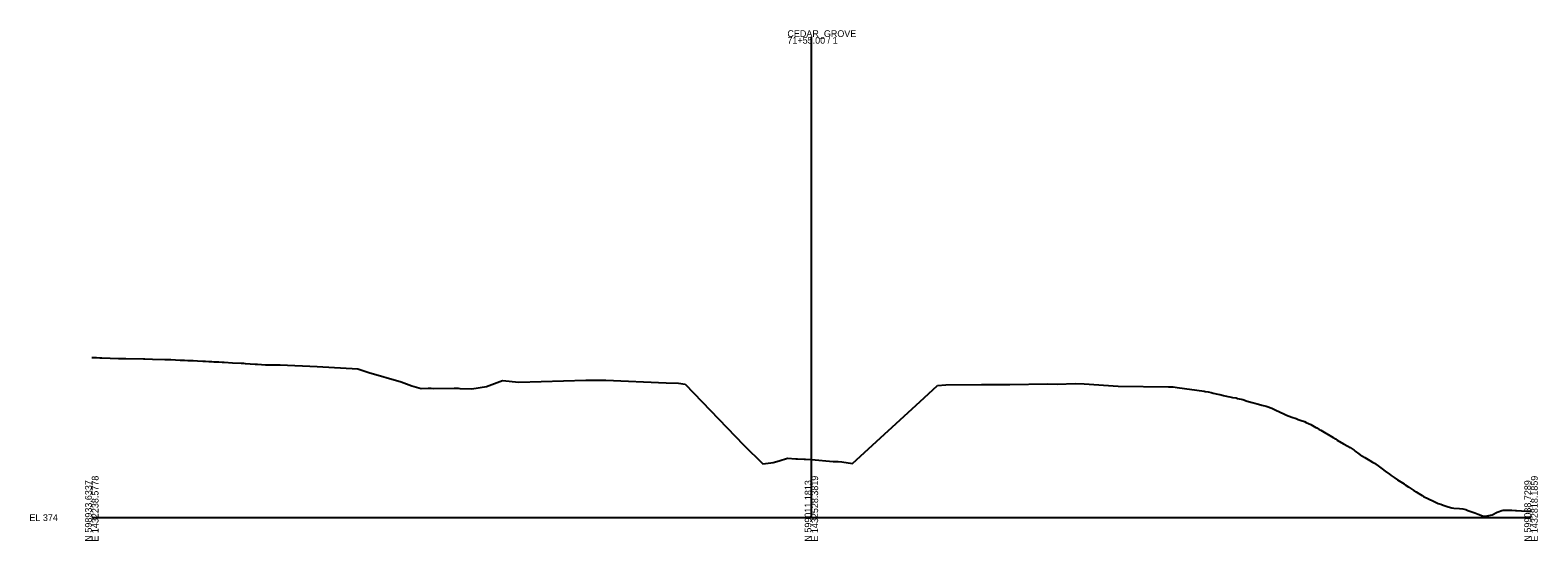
# Model space of a CAD drawing. Extents: x -26 to 2203, y -10 to 12201.
# Drawn here: x 1574 to 2203, y -10 to 203 of the extents above; entities that cross this region are included whole.
import ezdxf

# ---------------------------------------------------------------- set-up
doc = ezdxf.new("R2010")
doc.units = 0
doc.layers.add('DESIGN - SHEET - Light Grid', color=7, linetype='Continuous')
doc.layers.add('SURVEY - GROUND - Top of Ground', color=7, linetype='Continuous')

msp = doc.modelspace()

# ---------------------------------------------------------------- linework, layer by layer
at = {"layer": 'DESIGN - SHEET - Light Grid'}
for p, q in [((1900, 0), (1900, 200.49)), ((1600, 0), (1900, 0)), ((1900, 0), (2200, 0))]:
    msp.add_line(p, q, dxfattribs=at)
at = {"layer": 'SURVEY - GROUND - Top of Ground'}
for p, q in [((1600, 66.83), (1600.82, 66.79)), ((1600.82, 66.79), (1601.9, 66.75)), ((1601.9, 66.75), (1603.41, 66.69)), ((1603.41, 66.69), (1604.13, 66.66)), ((1604.13, 66.66), (1611.17, 66.43)), ((1611.17, 66.43), (1614.15, 66.32)), ((1614.15, 66.32), (1621.52, 66.27)), ((1621.52, 66.27), (1622.09, 66.24)), ((1622.09, 66.24), (1625.29, 66.14)), ((1625.29, 66.14), (1630.49, 66)), ((1630.49, 66), (1631.1, 65.96)), ((1631.1, 65.96), (1631.88, 65.93)), ((1631.88, 65.93), (1632.89, 65.89)), ((1632.89, 65.89), (1636.81, 65.71)), ((1636.81, 65.71), (1638.65, 65.66)), ((1638.65, 65.66), (1640.1, 65.58)), ((1640.1, 65.58), (1642.23, 65.5)), ((1642.23, 65.5), (1644.01, 65.37)), ((1644.01, 65.37), (1646.34, 65.24)), ((1646.34, 65.24), (1647.4, 65.21)), ((1647.4, 65.21), (1648.86, 65.16)), ((1648.86, 65.16), (1649.99, 65.1)), ((1649.99, 65.1), (1650.9, 65.05)), ((1650.9, 65.05), (1652.58, 64.96)), ((1652.58, 64.96), (1652.94, 64.94)), ((1652.94, 64.94), (1654.3, 64.86)), ((1654.3, 64.86), (1655.17, 64.82)), ((1655.17, 64.82), (1658.69, 64.63)), ((1658.69, 64.63), (1662.23, 64.44)), ((1662.23, 64.44), (1662.93, 64.4)), ((1662.93, 64.4), (1663.3, 64.38)), ((1663.3, 64.38), (1663.98, 64.32)), ((1663.98, 64.32), (1668.11, 64)), ((1668.11, 64), (1668.51, 63.98)), ((1668.51, 63.98), (1669.1, 63.96)), ((1669.1, 63.96), (1672.37, 63.75)), ((1672.37, 63.75), (1678.59, 63.7)), ((1678.59, 63.7), (1694.02, 63.02)), ((1694.02, 63.02), (1710.9, 62.12)), ((1710.9, 62.12), (1715.55, 60.53)), ((1715.55, 60.53), (1728.91, 56.58)), ((1728.91, 56.58), (1733.49, 55.01)), ((1764.59, 54.71), (1771.19, 57.16)), ((1771.19, 57.16), (1778.02, 56.5)), ((1778.02, 56.5), (1806.01, 57.38)), ((1806.01, 57.38), (1808.13, 57.34)), ((1808.13, 57.34), (1814.31, 57.27)), ((1814.31, 57.27), (1839.43, 56.26)), ((1733.49, 55.01), (1737.26, 53.86)), ((1737.26, 53.86), (1740.18, 53.97)), ((1740.18, 53.97), (1741.55, 53.93)), ((1741.55, 53.93), (1742.51, 53.92)), ((1742.51, 53.92), (1751.03, 54.01)), ((1751.03, 54.01), (1751.57, 53.98)), ((1751.57, 53.98), (1752.73, 53.98)), ((1752.73, 53.98), (1753.42, 53.87)), ((1753.42, 53.87), (1758.4, 53.76)), ((1758.4, 53.76), (1764.59, 54.71)), ((1839.43, 56.26), (1844.6, 56.05)), ((1844.6, 56.05), (1847.35, 55.63)), ((1847.35, 55.63), (1871.78, 30.29)), ((1947.01, 49.9), (1952.51, 55.14)), ((1952.51, 55.14), (1955.97, 55.42)), ((1955.97, 55.42), (1970.92, 55.59)), ((1970.92, 55.59), (1978.28, 55.47)), ((1978.28, 55.47), (1982.74, 55.48)), ((1982.74, 55.48), (1998.38, 55.76)), ((1998.38, 55.76), (2002.63, 55.73)), ((2002.63, 55.73), (2009.95, 55.93)), ((2009.95, 55.93), (2013.71, 55.76)), ((2013.71, 55.76), (2027.9, 54.84)), ((2027.9, 54.84), (2048.8, 54.51)), ((2048.8, 54.51), (2050.87, 54.5)), ((2050.87, 54.5), (2052.5, 54.32)), ((2052.5, 54.32), (2063.67, 52.72)), ((2063.67, 52.72), (2064.09, 52.65)), ((2064.09, 52.65), (2065.38, 52.42)), ((2065.38, 52.42), (2066.68, 52.17)), ((2066.68, 52.17), (2067.42, 51.95)), ((2067.42, 51.95), (2069.46, 51.47)), ((2069.46, 51.47), (2070.2, 51.3)), ((2070.2, 51.3), (2071.85, 50.92)), ((2071.85, 50.92), (2073.55, 50.56)), ((2073.55, 50.56), (2074.44, 50.38)), ((2074.44, 50.38), (2075.59, 50.15)), ((1917.13, 22.6), (1947.01, 49.9)), ((2075.59, 50.15), (2077.03, 49.9)), ((2077.03, 49.9), (2077.63, 49.75)), ((2077.63, 49.75), (2079.87, 49.24)), ((2079.87, 49.24), (2081.71, 48.61)), ((2081.71, 48.61), (2082.21, 48.46)), ((2082.21, 48.46), (2083.76, 48.02)), ((2083.76, 48.02), (2084.8, 47.73)), ((2084.8, 47.73), (2085.8, 47.5)), ((2085.8, 47.5), (2087.38, 47.08)), ((2087.38, 47.08), (2087.84, 46.97)), ((2087.84, 46.97), (2089.55, 46.54)), ((2089.55, 46.54), (2089.97, 46.42)), ((2089.97, 46.42), (2091.92, 45.67)), ((2091.92, 45.67), (2092.56, 45.37)), ((2092.56, 45.37), (2093.66, 44.83)), ((2093.66, 44.83), (2095.15, 44.1)), ((2095.15, 44.1), (2097.19, 43.17)), ((2097.19, 43.17), (2097.74, 42.91)), ((2097.74, 42.91), (2098.05, 42.78)), ((2098.05, 42.78), (2099.22, 42.34)), ((2099.22, 42.34), (2100.32, 41.92)), ((2100.32, 41.92), (2102.13, 41.29)), ((2102.13, 41.29), (2102.91, 40.99)), ((2102.91, 40.99), (2104.17, 40.54)), ((2104.17, 40.54), (2105.5, 40.03)), ((2105.5, 40.03), (2106.22, 39.71)), ((2106.22, 39.71), (2108.26, 38.79)), ((2108.26, 38.79), (2108.89, 38.44)), ((2108.89, 38.44), (2110.3, 37.64)), ((2110.3, 37.64), (2110.68, 37.42)), ((2110.68, 37.42), (2111.61, 36.81)), ((2111.61, 36.81), (2112.34, 36.41)), ((2112.34, 36.41), (2117.48, 33.41)), ((2117.48, 33.41), (2118.44, 32.85)), ((2118.44, 32.85), (2119.24, 32.37)), ((2119.24, 32.37), (2121.85, 30.78)), ((1871.78, 30.29), (1879.77, 22.48)), ((2121.85, 30.78), (2123.62, 29.75)), ((2123.62, 29.75), (2124.59, 29.18)), ((2124.59, 29.18), (2126.2, 28.07)), ((2126.2, 28.07), (2126.63, 27.78)), ((2126.63, 27.78), (2128.24, 26.64)), ((2128.24, 26.64), (2128.79, 26.24)), ((2128.79, 26.24), (2130.72, 25.05)), ((1879.77, 22.48), (1883.04, 22.85)), ((1883.04, 22.85), (1884.11, 22.95)), ((1884.11, 22.95), (1886.6, 23.73)), ((1886.6, 23.73), (1890.03, 24.74)), ((1890.03, 24.74), (1893.55, 24.58)), ((1893.55, 24.58), (1894.18, 24.55)), ((1894.18, 24.55), (1896.99, 24.43)), ((1896.99, 24.43), (1897.47, 24.42)), ((1897.47, 24.42), (1900, 24.21)), ((1900, 24.21), (1909.03, 23.44)), ((1909.03, 23.44), (1909.37, 23.42)), ((1909.37, 23.42), (1909.91, 23.37)), ((1909.91, 23.37), (1911.11, 23.46)), ((1911.11, 23.46), (1912.66, 23.32)), ((1912.66, 23.32), (1917.13, 22.6)), ((2130.72, 25.05), (2131.38, 24.64)), ((2131.38, 24.64), (2132.76, 23.87)), ((2132.76, 23.87), (2133.97, 23.16)), ((2133.97, 23.16), (2134.8, 22.65)), ((2134.8, 22.65), (2136.84, 21.13)), ((2136.84, 21.13), (2137.91, 20.33)), ((2137.91, 20.33), (2139.15, 19.42)), ((2139.15, 19.42), (2140.93, 18.18)), ((2140.93, 18.18), (2141.73, 17.6)), ((2141.73, 17.6), (2142.97, 16.72)), ((2142.97, 16.72), (2144.32, 15.8)), ((2144.32, 15.8), (2147.05, 14.04)), ((2147.05, 14.04), (2147.58, 13.69)), ((2147.58, 13.69), (2149.09, 12.66)), ((2149.09, 12.66), (2149.5, 12.39)), ((2149.5, 12.39), (2151.13, 11.29)), ((2151.13, 11.29), (2152.09, 10.71)), ((2152.09, 10.71), (2153.18, 10.01)), ((2153.18, 10.01), (2154.67, 9.16)), ((2154.67, 9.16), (2155.22, 8.85)), ((2155.22, 8.85), (2157.26, 7.83)), ((2157.26, 7.83), (2159.3, 6.86)), ((2159.3, 6.86), (2159.85, 6.6)), ((2159.85, 6.6), (2161.34, 5.96)), ((2161.34, 5.96), (2162.44, 5.56)), ((2162.44, 5.56), (2163.39, 5.2)), ((2163.39, 5.2), (2165.03, 4.65)), ((2165.03, 4.65), (2165.43, 4.57)), ((2165.43, 4.57), (2166.92, 4.15)), ((2166.92, 4.15), (2167.87, 3.96)), ((2167.87, 3.96), (2170.2, 3.82)), ((2170.2, 3.82), (2171.55, 3.63)), ((2171.55, 3.63), (2172.79, 3.32)), ((2172.79, 3.32), (2173.59, 3.04)), ((2173.59, 3.04), (2175.38, 2.39)), ((2175.38, 2.39), (2176.6, 1.93)), ((2176.6, 1.93), (2177.97, 1.41)), ((2177.97, 1.41), (2179.72, 0.79)), ((2179.72, 0.79), (2180.56, 0.61)), ((2180.56, 0.61), (2181.76, 0.71)), ((2181.76, 0.71), (2183.14, 0.97)), ((2183.14, 0.97), (2183.8, 1.16)), ((2183.8, 1.16), (2185.84, 2.26)), ((2185.84, 2.26), (2186.27, 2.44)), ((2186.27, 2.44), (2187.89, 2.98)), ((2187.89, 2.98), (2188.32, 3.11)), ((2188.32, 3.11), (2189.07, 3.14)), ((2189.07, 3.14), (2190.91, 3.18)), ((2190.91, 3.18), (2191.97, 3.12)), ((2191.97, 3.12), (2193.5, 2.98)), ((2193.5, 2.98), (2194.01, 2.94)), ((2194.01, 2.94), (2196.08, 2.77)), ((2196.08, 2.77), (2198.1, 2.73)), ((2198.1, 2.73), (2198.67, 2.71)), ((2198.67, 2.71), (2200, 2.72))]:
    msp.add_line(p, q, dxfattribs=at)

# ---------------------------------------------------------------- texts
at = {"layer": 'DESIGN - SHEET - Light Grid'}
for s, p in [('CEDAR_GROVE', (1890, 200.49)), ('71+55.00 / 1', (1890, 197.69)), ('EL 374', (1574, -1.4))]:
    msp.add_text(s, height=2.8, dxfattribs=at).set_placement(p)
for s, p in [('N 598933.6337', (1600, -10)), ('E 1432238.5778', (1602.8, -10)), ('N 599011.1813', (1900, -10)), ('E 1432528.3819', (1902.8, -10)), ('N 599088.7289', (2200, -10)), ('E 1432818.1859', (2202.8, -10))]:
    msp.add_text(s, height=2.8, rotation=90, dxfattribs=at).set_placement(p)

doc.saveas('drawing.dxf')
